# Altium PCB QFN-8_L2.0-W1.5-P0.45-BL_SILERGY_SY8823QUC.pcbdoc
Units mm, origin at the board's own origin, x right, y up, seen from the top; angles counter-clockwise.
Board outline 15.45 x 14.5 mm, 2 copper layers (Top Layer, Bottom Layer), stack 0 mm thick; 1 components, 0 nets, 8 pads, 0 vias.
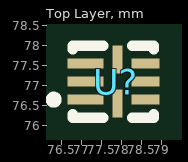
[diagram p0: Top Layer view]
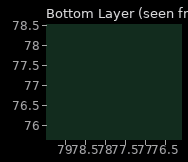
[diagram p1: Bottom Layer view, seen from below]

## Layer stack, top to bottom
Top Layer: signal copper (thickness not stored)
Bottom Layer: signal copper (thickness not stored)

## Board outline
85.3,69.85 69.85,69.85 69.85,84.35 85.3,84.35

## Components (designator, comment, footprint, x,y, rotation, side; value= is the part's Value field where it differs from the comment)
U? "" QFN-8_L2.0-W1.5-P0.45-BL_SILERGY_SY8823QUC 77.85,77.1 r0 top

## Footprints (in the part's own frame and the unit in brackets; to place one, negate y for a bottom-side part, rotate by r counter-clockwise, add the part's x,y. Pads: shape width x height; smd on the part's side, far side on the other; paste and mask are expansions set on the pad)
QFN-8_L2.0-W1.5-P0.45-BL_SILERGY_SY8823QUC [mm]
  rect 0.9x0.25 smd paste+0 mask+0.05: 1(-0.75,-0.45) 2(-0.75,0) 3(-0.75,0.45)
  rect 0.25x0.7 smd paste+0 mask+0.05: 4(0.05,0.55) 8(0.05,-0.55)
  rect 0.7x0.25 smd paste+0 mask+0.05: 5(0.75,0.45) 6(0.75,0) 7(0.75,-0.45)
  silkscreen extent -1.65,-0.9 0.95,0.9

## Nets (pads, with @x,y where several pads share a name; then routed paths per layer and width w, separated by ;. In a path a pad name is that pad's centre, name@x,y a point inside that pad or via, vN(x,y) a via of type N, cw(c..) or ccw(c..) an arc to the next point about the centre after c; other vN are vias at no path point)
pads on no net: U?.1 U?.2 U?.3 U?.4 U?.5 U?.6 U?.7 U?.8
